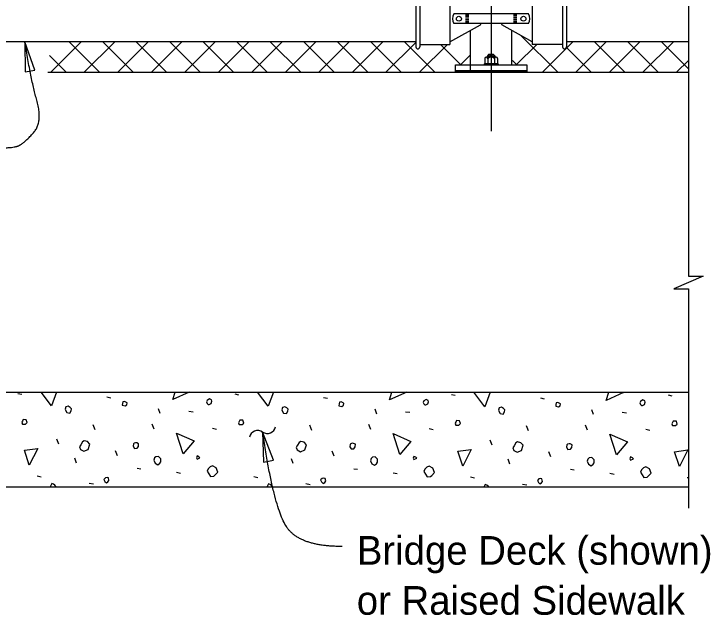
# Model space of a CAD drawing. Extents: x 0 to 41.1, y 0 to 25.9.
# Drawn here: x 18.718 to 23.587, y 13.138 to 17.368 of the extents above; entities that cross this region are included whole.
import ezdxf

# ---------------------------------------------------------------- set-up
doc = ezdxf.new("R2010")
doc.units = 0
for name, color, linetype in [('CL_Major', 7, 'Continuous'), ('Dimension', 7, 'Continuous'), ('Miscellaneous', 7, 'Continuous'), ('SteelMisc', 7, 'Continuous'), ('SupstrConc', 7, 'Continuous')]:
    doc.layers.add(name, color=color, linetype=linetype)

msp = doc.modelspace()

# ---------------------------------------------------------------- linework, layer by layer
at = {"layer": 'CL_Major'}
msp.add_line((22.075, 25.3255), (22.075, 16.5436), dxfattribs=at)
at = {"layer": 'Dimension'}
msp.add_line((22.075, 17.0171), (22.075, 17.0164), dxfattribs=at)
for points in [[(23.462, 20.0194), (23.462, 19.0017), (23.5654, 19.0017), (23.462, 18.9567), (23.3587, 18.9117), (23.462, 18.9117), (23.462, 16.9573)], [(23.462, 16.9573), (23.462, 15.5233), (23.5654, 15.5233), (23.462, 15.4783), (23.3587, 15.4333), (23.462, 15.4333), (23.462, 13.8908)]]:
    msp.add_lwpolyline(points, dxfattribs=at)
for points in [[(18.7961, 17.1708), (18.7977, 16.9596), (18.8671, 16.9719)], [(20.4681, 14.4269), (20.4742, 14.2157), (20.5434, 14.2295)]]:
    msp.add_lwpolyline(points, close=True, dxfattribs=at)
for centre, start, end in [((20.501, 14.4756), 235.4525, 347.1798), ((20.4334, 14.3774), 55.4525, 167.1798)]:
    msp.add_arc(centre, 0.0596, start, end, dxfattribs=at)
for points in [[(18.4847, 16.4238), (18.7076, 16.4203), (18.7925, 16.4592), (18.9233, 16.6079), (18.8385, 16.9053), (18.796, 17.1707)], [(21.0265, 13.6215), (20.7379, 13.6215), (20.5488, 13.877), (20.468, 14.4269)]]:
    msp.add_open_spline(points, degree=2, dxfattribs=at)
at = {"layer": 'Miscellaneous'}
for p, q in [((22.2843, 17.2162), (22.5432, 16.9573)), ((18.9782, 16.9573), (19.1918, 17.1708)), ((19.1078, 17.1708), (19.3214, 16.9573)), ((19.2139, 16.9573), (19.4275, 17.1708)), ((19.3436, 17.1708), (19.5571, 16.9573)), ((19.4496, 16.9573), (19.6632, 17.1708)), ((19.5793, 17.1708), (19.7928, 16.9573)), ((19.6853, 16.9573), (19.8989, 17.1708)), ((19.815, 17.1708), (20.0285, 16.9573)), ((19.921, 16.9573), (20.1346, 17.1708)), ((20.0507, 17.1708), (20.2642, 16.9573)), ((20.1567, 16.9573), (20.3703, 17.1708)), ((20.2864, 17.1708), (20.4999, 16.9573)), ((20.3924, 16.9573), (20.606, 17.1708)), ((20.5221, 17.1708), (20.7356, 16.9573)), ((20.6281, 16.9573), (20.8417, 17.1708)), ((20.7578, 17.1708), (20.9713, 16.9573)), ((20.8639, 16.9573), (21.0774, 17.1708)), ((20.9935, 17.1708), (21.207, 16.9573)), ((21.0996, 16.9573), (21.3131, 17.1708)), ((21.2292, 17.1708), (21.4427, 16.9573)), ((21.3353, 16.9573), (21.5457, 17.1677)), ((21.4649, 17.1708), (21.6784, 16.9573)), ((21.571, 16.9573), (21.7673, 17.1536)), ((21.7178, 17.1536), (21.862, 17.0093)), ((22.2521, 17.0093), (22.3963, 17.1536)), ((22.4357, 16.9573), (22.6493, 17.1708)), ((22.6714, 16.9573), (22.885, 17.1708)), ((22.8011, 17.1708), (23.0146, 16.9573)), ((22.9071, 16.9573), (23.1207, 17.1708)), ((23.0368, 17.1708), (23.2503, 16.9573)), ((23.1428, 16.9573), (23.3564, 17.1708)), ((23.2725, 17.1708), (23.462, 16.9813)), ((22.6044, 17.1318), (22.7789, 16.9573)), ((18.9682, 17.0747), (19.0857, 16.9573)), ((21.8587, 17.0093), (21.9292, 17.0798)), ((22.0638, 17.0788), (22.0846, 17.0788)), ((22.0638, 17.0691), (22.0846, 17.0691)), ((22.2241, 17.0406), (22.2554, 17.0093)), ((23.3785, 16.9573), (23.462, 17.0407)), ((21.825, 16.9642), (22.325, 16.9642)), ((21.825, 16.9607), (22.325, 16.9607)), ((18.7476, 14.6982), (18.7741, 14.6929)), ((19.3734, 14.6734), (19.3999, 14.6681)), ((20.2714, 14.6946), (20.2979, 14.6893)), ((20.8972, 14.6699), (20.9237, 14.6646)), ((21.7952, 14.6911), (21.8217, 14.6858)), ((22.421, 14.6664), (22.4475, 14.6611)), ((23.319, 14.6876), (23.3456, 14.6823)), ((19.7482, 14.5568), (19.7358, 14.5904)), ((19.9479, 14.5727), (19.9797, 14.5691)), ((21.272, 14.5532), (21.2596, 14.5868)), ((21.4717, 14.5691), (21.5036, 14.5656)), ((22.7958, 14.5497), (22.7834, 14.5833)), ((22.9955, 14.5656), (23.0274, 14.5621)), ((19.2903, 14.4419), (19.2762, 14.4772)), ((19.7057, 14.4472), (19.6916, 14.4825)), ((20.8141, 14.4383), (20.8, 14.4737)), ((21.2295, 14.4436), (21.2154, 14.479)), ((22.3379, 14.4348), (22.3238, 14.4701)), ((22.7534, 14.4401), (22.7392, 14.4754)), ((20.1159, 14.4542), (20.1441, 14.4472)), ((21.6397, 14.4507), (21.668, 14.4436)), ((23.1635, 14.4472), (23.1918, 14.4401)), ((19.034, 14.3411), (19.0198, 14.3765)), ((22.0816, 14.334), (22.0675, 14.3694)), ((19.4476, 14.2598), (19.4335, 14.2951)), ((20.9715, 14.2562), (20.9573, 14.2916)), ((22.4953, 14.2527), (22.4811, 14.2881)), ((19.1595, 14.2085), (19.1471, 14.2421)), ((20.6833, 14.205), (20.6709, 14.2386)), ((22.2071, 14.2014), (22.1947, 14.235)), ((19.5855, 14.1714), (19.6103, 14.1679)), ((21.1093, 14.1679), (21.1341, 14.1643)), ((19.8613, 14.1431), (19.8913, 14.1378)), ((21.3851, 14.1396), (21.4152, 14.1343)), ((22.6332, 14.1643), (22.6579, 14.1608)), ((22.9089, 14.136), (22.939, 14.1307)), ((18.882, 14.1184), (18.9102, 14.1113)), ((20.4058, 14.1148), (20.4341, 14.1077)), ((21.9296, 14.1113), (21.9579, 14.1042)), ((23.4534, 14.1077), (23.462, 14.1056)), ((19.2479, 14.0671), (19.2779, 14.0618)), ((19.9981, 14.0406), (19.9974, 14.0423)), ((20.7717, 14.0636), (20.8017, 14.0583)), ((22.2955, 14.06), (22.3256, 14.0547))]:
    msp.add_line(p, q, dxfattribs=at)
msp.add_lwpolyline([(21.825, 16.9677), (22.325, 16.9677), (22.325, 16.9573), (21.825, 16.9573)], close=True, dxfattribs=at)
for points in [[(18.9827, 14.6116), (18.91, 14.7072)], [(19.0185, 14.7072), (18.9827, 14.6116)], [(19.8365, 14.6558), (19.8524, 14.7072)], [(19.9511, 14.7072), (19.8365, 14.6558)], [(20.5065, 14.608), (20.4311, 14.7072)], [(20.5436, 14.7072), (20.5065, 14.608)], [(21.3604, 14.6522), (21.3773, 14.7072)], [(21.4818, 14.7072), (21.4823, 14.707), (21.3604, 14.6522)], [(22.0303, 14.6045), (21.9523, 14.7072)], [(22.0687, 14.7072), (22.0303, 14.6045)], [(22.8842, 14.6487), (22.9022, 14.7072)], [(22.9967, 14.7072), (23.0062, 14.7035), (22.8842, 14.6487)], [(20.084, 14.6204), (20.0911, 14.6204), (20.1052, 14.6275), (20.1106, 14.6434), (20.1088, 14.6522), (20.0946, 14.6593), (20.077, 14.6487), (20.0734, 14.6381), (20.077, 14.6275), (20.084, 14.6204)], [(21.6078, 14.6169), (21.6149, 14.6169), (21.6291, 14.6239), (21.6344, 14.6398), (21.6326, 14.6487), (21.6185, 14.6558), (21.6008, 14.6452), (21.5972, 14.6345), (21.6008, 14.6239), (21.6078, 14.6169)], [(19.0817, 14.5797), (19.0905, 14.5638), (19.1118, 14.5603), (19.1206, 14.5762), (19.1241, 14.5904), (19.1153, 14.5992), (19.0994, 14.608), (19.0835, 14.6027), (19.0782, 14.5868), (19.0817, 14.5797)], [(19.4812, 14.6151), (19.5007, 14.6098), (19.513, 14.6186), (19.5148, 14.631), (19.5113, 14.6345), (19.4971, 14.6416), (19.4848, 14.6398), (19.483, 14.6275), (19.4812, 14.6151)], [(21.005, 14.6116), (21.0245, 14.6063), (21.0369, 14.6151), (21.0386, 14.6275), (21.0351, 14.631), (21.021, 14.6381), (21.0086, 14.6363), (21.0068, 14.6239), (21.005, 14.6116)], [(22.5289, 14.608), (22.5483, 14.6027), (22.5607, 14.6116), (22.5624, 14.6239), (22.5589, 14.6275), (22.5448, 14.6345), (22.5324, 14.6328), (22.5306, 14.6204), (22.5289, 14.608)], [(23.1317, 14.6133), (23.1387, 14.6133), (23.1529, 14.6204), (23.1582, 14.6363), (23.1564, 14.6452), (23.1423, 14.6522), (23.1246, 14.6416), (23.1211, 14.631), (23.1246, 14.6204), (23.1317, 14.6133)], [(20.6055, 14.5762), (20.6144, 14.5603), (20.6356, 14.5568), (20.6444, 14.5727), (20.648, 14.5868), (20.6391, 14.5957), (20.6232, 14.6045), (20.6073, 14.5992), (20.602, 14.5833), (20.6055, 14.5762)], [(22.1293, 14.5727), (22.1382, 14.5568), (22.1594, 14.5532), (22.1682, 14.5691), (22.1718, 14.5833), (22.1629, 14.5921), (22.147, 14.601), (22.1311, 14.5957), (22.1258, 14.5797), (22.1293, 14.5727)], [(18.7794, 14.4825), (18.8006, 14.4825), (18.8112, 14.4931), (18.8059, 14.5126), (18.783, 14.5143), (18.7794, 14.5037), (18.7741, 14.4949), (18.7794, 14.4825), (18.7759, 14.4861)], [(20.3032, 14.479), (20.3244, 14.479), (20.3351, 14.4896), (20.3298, 14.509), (20.3068, 14.5108), (20.3032, 14.5002), (20.2979, 14.4914), (20.3032, 14.479), (20.2997, 14.4825)], [(21.8271, 14.4754), (21.8483, 14.4754), (21.8589, 14.4861), (21.8536, 14.5055), (21.8306, 14.5073), (21.8271, 14.4967), (21.8217, 14.4878), (21.8271, 14.4754), (21.8235, 14.479)], [(23.3509, 14.4719), (23.3721, 14.4719), (23.3827, 14.4825), (23.3774, 14.502), (23.3544, 14.5037), (23.3509, 14.4931), (23.3456, 14.4843), (23.3509, 14.4719), (23.3473, 14.4754)], [(19.909, 14.2722), (19.8613, 14.4189), (19.9868, 14.3641), (19.909, 14.2722)], [(21.4328, 14.2686), (21.3851, 14.4153), (21.5106, 14.3605), (21.4328, 14.2686)], [(22.9567, 14.2651), (22.9089, 14.4118), (23.0344, 14.357), (22.9567, 14.2651)], [(19.1878, 14.304), (19.2108, 14.2916), (19.2408, 14.304), (19.2532, 14.3411), (19.2355, 14.3588), (19.2125, 14.3641), (19.2019, 14.357), (19.1895, 14.3376), (19.1807, 14.3216), (19.1878, 14.304)], [(19.5572, 14.327), (19.5661, 14.311), (19.5855, 14.3128), (19.5944, 14.3252), (19.5961, 14.3446), (19.5838, 14.3499), (19.5749, 14.3517), (19.5643, 14.3482), (19.5608, 14.3446), (19.5572, 14.327)], [(20.7116, 14.3004), (20.7346, 14.2881), (20.7646, 14.3004), (20.777, 14.3376), (20.7593, 14.3552), (20.7363, 14.3605), (20.7257, 14.3535), (20.7134, 14.334), (20.7045, 14.3181), (20.7116, 14.3004)], [(21.0811, 14.3234), (21.0899, 14.3075), (21.1093, 14.3093), (21.1182, 14.3216), (21.1199, 14.3411), (21.1076, 14.3464), (21.0987, 14.3482), (21.0881, 14.3446), (21.0846, 14.3411), (21.0811, 14.3234)], [(22.2354, 14.2969), (22.2584, 14.2845), (22.2884, 14.2969), (22.3008, 14.334), (22.2831, 14.3517), (22.2602, 14.357), (22.2495, 14.3499), (22.2372, 14.3305), (22.2283, 14.3146), (22.2354, 14.2969)], [(22.6049, 14.3199), (22.6137, 14.304), (22.6332, 14.3057), (22.642, 14.3181), (22.6438, 14.3376), (22.6314, 14.3429), (22.6225, 14.3446), (22.6119, 14.3411), (22.6084, 14.3376), (22.6049, 14.3199)], [(18.8272, 14.1944), (18.7936, 14.2987), (18.8873, 14.311), (18.8272, 14.1944)], [(21.8748, 14.1873), (21.8412, 14.2916), (21.9349, 14.304), (21.8748, 14.1873)], [(23.3986, 14.1838), (23.365, 14.2881), (23.4587, 14.3004), (23.3986, 14.1838)], [(19.7022, 14.228), (19.7128, 14.2067), (19.7305, 14.1961), (19.7446, 14.2067), (19.7517, 14.2174), (19.7517, 14.2386), (19.7358, 14.2545), (19.7163, 14.2527), (19.7075, 14.2439), (19.7022, 14.228)], [(20.008, 14.2368), (20.0275, 14.2456), (20.0204, 14.2527), (20.008, 14.258), (20.0027, 14.2456), (20.008, 14.2368)], [(21.226, 14.2244), (21.2366, 14.2032), (21.2543, 14.1926), (21.2684, 14.2032), (21.2755, 14.2138), (21.2755, 14.235), (21.2596, 14.2509), (21.2402, 14.2492), (21.2313, 14.2403), (21.226, 14.2244)], [(21.5318, 14.2333), (21.5513, 14.2421), (21.5442, 14.2492), (21.5318, 14.2545), (21.5265, 14.2421), (21.5318, 14.2333)], [(22.7498, 14.2209), (22.7604, 14.1997), (22.7781, 14.1891), (22.7923, 14.1997), (22.7993, 14.2103), (22.7993, 14.2315), (22.7834, 14.2474), (22.764, 14.2456), (22.7551, 14.2368), (22.7498, 14.2209)], [(23.0556, 14.2297), (23.0751, 14.2386), (23.068, 14.2456), (23.0556, 14.2509), (23.0503, 14.2386), (23.0556, 14.2297)], [(20.0787, 14.1519), (20.1017, 14.1148), (20.1247, 14.1166), (20.1335, 14.1254), (20.153, 14.1449), (20.1406, 14.1749), (20.1159, 14.1891), (20.0982, 14.182), (20.084, 14.1679), (20.0787, 14.1519)], [(21.6025, 14.1484), (21.6255, 14.1113), (21.6485, 14.1131), (21.6573, 14.1219), (21.6768, 14.1413), (21.6644, 14.1714), (21.6397, 14.1855), (21.622, 14.1785), (21.6078, 14.1643), (21.6025, 14.1484)], [(23.1264, 14.1449), (23.1493, 14.1077), (23.1723, 14.1095), (23.1812, 14.1184), (23.2006, 14.1378), (23.1882, 14.1679), (23.1635, 14.182), (23.1458, 14.1749), (23.1317, 14.1608), (23.1264, 14.1449)], [(19.3592, 14.0795), (19.3699, 14.0689), (19.3805, 14.0759), (19.3875, 14.0865), (19.384, 14.1042), (19.3752, 14.106), (19.3628, 14.1042), (19.3522, 14.0936), (19.3592, 14.0795)], [(20.8831, 14.0759), (20.8937, 14.0653), (20.9043, 14.0724), (20.9113, 14.083), (20.9078, 14.1007), (20.899, 14.1024), (20.8866, 14.1007), (20.876, 14.0901), (20.8831, 14.0759)], [(22.4069, 14.0724), (22.4175, 14.0618), (22.4281, 14.0689), (22.4352, 14.0795), (22.4316, 14.0971), (22.4228, 14.0989), (22.4104, 14.0971), (22.3998, 14.0865), (22.4069, 14.0724)], [(19.0116, 14.0406), (19.0128, 14.0441), (19.0075, 14.0529), (18.9969, 14.06), (18.9845, 14.0653), (18.9774, 14.0512), (18.9739, 14.0406)], [(20.5366, 14.0406), (20.5313, 14.0494), (20.5207, 14.0565), (20.5083, 14.0618), (20.5012, 14.0476), (20.4989, 14.0406)], [(22.0583, 14.0406), (22.0551, 14.0459), (22.0445, 14.0529), (22.0321, 14.0583), (22.025, 14.0441), (22.0239, 14.0406)]]:
    msp.add_lwpolyline(points, dxfattribs=at)
at = {"layer": 'SteelMisc'}
for p, q in [((21.5457, 17.4454), (21.5457, 17.1357)), ((21.5725, 17.4454), (21.5725, 17.1357)), ((22.5775, 17.4454), (22.5775, 17.1357)), ((22.6044, 17.4454), (22.6044, 17.1357)), ((21.7855, 17.4258), (21.7855, 17.1536)), ((22.3646, 17.4258), (22.3646, 17.1536)), ((22.3374, 17.3685), (21.8126, 17.3685)), ((21.895, 17.3607), (21.9185, 17.3607)), ((21.895, 17.3511), (21.9185, 17.3511)), ((21.895, 17.3402), (21.9185, 17.3402)), ((22.255, 17.3607), (22.2316, 17.3607)), ((22.255, 17.3511), (22.2316, 17.3511)), ((22.255, 17.3402), (22.2316, 17.3402)), ((21.7855, 17.1717), (21.9994, 17.2902)), ((22.3374, 17.3007), (21.8126, 17.3007)), ((21.895, 17.3285), (21.9185, 17.3285)), ((21.895, 17.3167), (21.9185, 17.3167)), ((21.895, 17.3069), (21.9185, 17.3069)), ((22.3646, 17.1717), (22.1506, 17.2902)), ((22.255, 17.3285), (22.2316, 17.3285)), ((22.255, 17.3167), (22.2316, 17.3167)), ((22.255, 17.3069), (22.2316, 17.3069)), ((21.9292, 16.9573), (21.9292, 17.2513)), ((22.2209, 17.0093), (22.2209, 17.2513)), ((21.5457, 17.1708), (12.6044, 17.1708)), ((21.5725, 17.1536), (21.7855, 17.1536)), ((22.5775, 17.1536), (22.3646, 17.1536)), ((23.462, 17.1708), (22.6044, 17.1708)), ((22.0296, 17.054), (22.0296, 17.0164)), ((22.1091, 17.0627), (22.0409, 17.0627)), ((22.0589, 17.0837), (22.0492, 17.074)), ((22.0492, 17.074), (22.0492, 17.0627)), ((22.0492, 17.074), (22.1007, 17.074)), ((22.0523, 17.0543), (22.0523, 17.0164)), ((22.0589, 17.0837), (22.0894, 17.0837)), ((22.0894, 17.0837), (22.1007, 17.074)), ((22.0977, 17.0543), (22.0977, 17.0164)), ((22.1007, 17.074), (22.1007, 17.0627)), ((22.1204, 17.054), (22.1204, 17.0164)), ((22.0253, 17.0164), (22.0253, 17.0093)), ((22.0253, 17.0164), (22.1247, 17.0164)), ((22.1204, 17.0164), (22.0296, 17.0164)), ((22.1247, 17.0164), (22.1247, 17.0093)), ((21.9552, 16.9677), (22.1948, 16.9677))]:
    msp.add_line(p, q, dxfattribs=at)
msp.add_lwpolyline([(21.825, 17.0093), (22.325, 17.0093), (22.325, 16.9677), (21.825, 16.9677)], close=True, dxfattribs=at)
for centre, radius, start, end in [((21.5592, 17.1355), 0.0134, 180, 0), ((22.5909, 17.1355), 0.0134, 180, 0), ((22.041, 17.0509), 0.0118, 16.5986, 164.7005), ((22.075, 17.028), 0.0347, 49.2015, 130.7985), ((22.109, 17.051), 0.0118, 15.1506, 163.5042)]:
    msp.add_arc(centre, radius, start, end, dxfattribs=at)
for centre, major_axis, start_param, end_param in [((21.8818, 17.3345), (-0.0776, 0), 5.810211, 6.75616), ((22.2683, 17.3345), (0.0776, 0), 5.810211, 6.75616), ((21.8618, 17.3365), (0.146, 0), 5.947976, 6.024627), ((22.2882, 17.3365), (-0.146, 0), 0.258558, 0.335209)]:
    msp.add_ellipse(centre, major_axis=major_axis, ratio=0.957868, start_param=start_param, end_param=end_param, dxfattribs=at)
for centre, major_axis in [((21.8485, 17.334), (0.0178, 0)), ((22.3016, 17.334), (-0.0178, 0))]:
    msp.add_ellipse(centre, major_axis=major_axis, ratio=0.957868, dxfattribs=at)
at = {"layer": 'SupstrConc'}
for p, q in [((18.9581, 16.9573), (23.462, 16.9573)), ((0.6881, 14.7072), (23.462, 14.7072)), ((0.6881, 14.0406), (23.462, 14.0406))]:
    msp.add_line(p, q, dxfattribs=at)

# ---------------------------------------------------------------- texts
at = {"layer": 'Dimension'}
for s, p in [('Bridge Deck (shown)', (21.1302, 13.4931)), ('or Raised Sidewalk', (21.1302, 13.1411))]:
    msp.add_text(s, height=0.2016, dxfattribs=at).set_placement(p)

doc.saveas('drawing.dxf')
